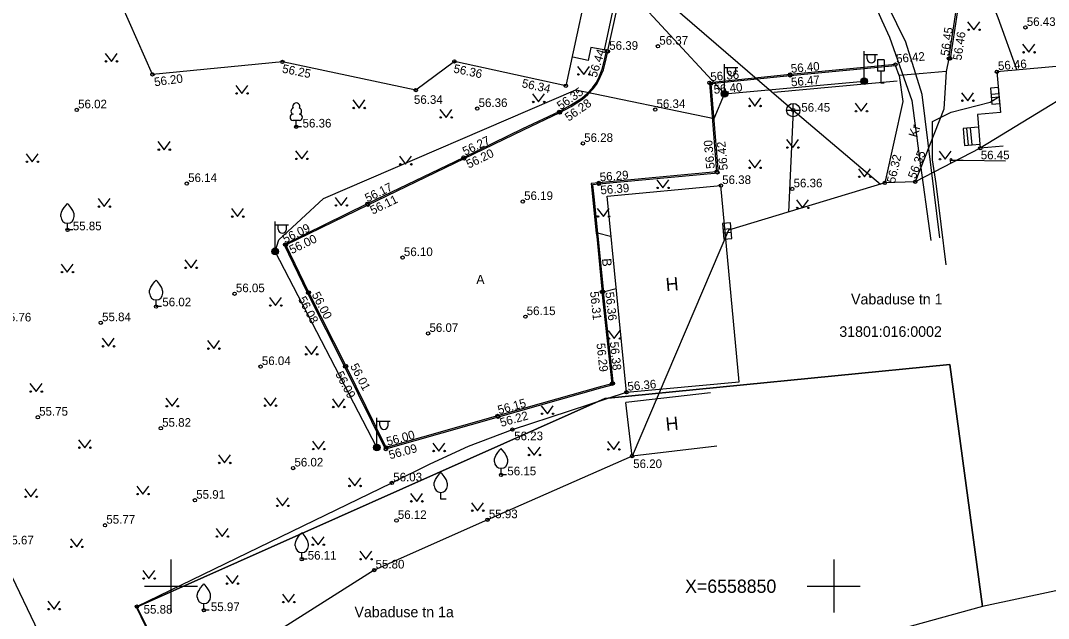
# Model space of a CAD drawing. Extents: x 542320 to 543602, y 6558748 to 6559969.
# Drawn here: x 543038.7 to 543116.2, y 6558847.6 to 6558892.7 of the extents above; entities that cross this region are included whole.
import ezdxf

# ---------------------------------------------------------------- set-up
doc = ezdxf.new("R2010")
doc.units = 0
for name, color, linetype in [('AED', 7, 'Continuous'), ('ELRAJATISMP', 7, 'Continuous'), ('HALJASTUS', 7, 'Continuous'), ('HOONE', 7, 'Continuous'), ('HOONEDET', 7, 'Continuous'), ('KKAEV', 7, 'Continuous'), ('KORGUS-EH2000', 7, 'Continuous'), ('KTRASS', 7, 'Continuous'), ('LIIKLUS', 7, 'Continuous'), ('mootpiir', 7, 'Continuous'), ('MPKAABEL', 7, 'Continuous'), ('PIIR', 7, 'Continuous'), ('POST', 7, 'Continuous'), ('PUU', 7, 'Continuous'), ('SITRASS', 7, 'Continuous'), ('TEE', 7, 'Continuous'), ('VORK', 7, 'Continuous'), ('VTRASS', 7, 'Continuous')]:
    doc.layers.add(name, color=color, linetype=linetype)

# ---------------------------------------------------------------- blocks, each defined once
blk = doc.blocks.new('VKORIS')
for p, q in [((0, 4), (0, -4)), ((-4, 0), (4, 0))]:
    blk.add_line(p, q)
blk = doc.blocks.new('LEHTP1')
for p, q in [((0.48, 0.95), (-0.48, 0.95)), ((0, 0), (0, 0.95)), ((0.76, 0), (0, 0))]:
    blk.add_line(p, q)
for centre, radius, start, end in [((0, 3.04), 0.554, 332.5799, 207.4201), ((-0.47, 1.42), 0.475, 90.0016, 269.3953), ((-0.34, 2.35), 0.465, 109.0217, 253.1415), ((0.34, 2.35), 0.465, 286.8508, 70.9859), ((0.47, 1.42), 0.475, 270.6047, 89.9984)]:
    blk.add_arc(centre, radius, start, end)
blk = doc.blocks.new('VILJA1')
for p, q in [((0, 0), (0, 1)), ((0.8, 0), (0, 0))]:
    blk.add_line(p, q)
for points in [[(-1, 2), (-1, 2.3), (-0.98, 2.43), (-0.91, 2.69), (-0.79, 2.93), (-0.5, 3.4), (-0.18, 3.81), (0, 4)], [(1, 2), (1, 2.3), (0.98, 2.43), (0.91, 2.69), (0.79, 2.93), (0.5, 3.4), (0.18, 3.81), (0, 4)]]:
    blk.add_lwpolyline(points)
blk.add_arc((0, 2), 1, 180, 0)
blk = doc.blocks.new('MEPOST')
for radius in [0.5, 0.45, 0.4, 0.35, 0.3, 0.25, 0.2, 0.15, 0.1, 0.05]:
    blk.add_circle((0, 0), radius)
blk = doc.blocks.new('VAPOST')
for p, q in [((0, 0.5), (0, 4.5)), ((0, 4), (2, 4)), ((0.45, 3.36), (0.45, 4)), ((1.68, 3.36), (1.68, 4))]:
    blk.add_line(p, q)
blk.add_arc((1.07, 3.36), 0.613, 180, 0)
blk = doc.blocks.new('KAKAEV')
for p, q in [((-1, 0), (1, 0)), ((0, -1), (0, 1))]:
    blk.add_line(p, q)
blk.add_circle((0, 0), 1)
blk = doc.blocks.new('LIIKLM')
for points in [[(-0.5, 3.5), (-0.5, 1.8)], [(0.5, 3.5), (-0.5, 3.5)], [(0.5, 3.5), (0.5, 1.8)], [(0.5, 1.8), (-0.5, 1.8)], [(0, 1.8), (0, 0)], [(0.5, 0), (0, 0)]]:
    blk.add_lwpolyline(points)
blk = doc.blocks.new('ELKAPP')
for p, q in [((1.19, 0.6), (-1.19, 0.6)), ((-1.19, 0.6), (-1.19, -0.6)), ((-0.27, 0.6), (-0.27, -0.6)), ((0.27, 0.6), (0.27, -0.6)), ((1.19, -0.6), (1.19, 0.6)), ((-1.19, -0.6), (1.19, -0.6))]:
    blk.add_line(p, q)
blk = doc.blocks.new('MURU')
for p, q in [((-0.93, 1.21), (0, 0)), ((0, 0), (0.89, 1.21))]:
    blk.add_line(p, q)
for centre in [(-0.8, 0), (0.86, 0)]:
    blk.add_circle(centre, 0.11)
blk = doc.blocks.new('RING02')
blk.add_circle((0, 0), 0.25)

msp = doc.modelspace()

# ---------------------------------------------------------------- linework, layer by layer
at = {"layer": 'AED'}
msp.add_lwpolyline([(543050.102, 6558843.068), (543047.43, 6558848.45), (543066.668, 6558857.787), (543069.546, 6558859.237), (543072.445, 6558860.561), (543075.754, 6558861.81), (543084.367, 6558864.629)], dxfattribs=at)
at = {"layer": 'HALJASTUS'}
for points in [[(543095.485, 6558887.284), (543104.792, 6558888.136)], [(543034.867, 6558857.188), (543041.705, 6558842.986)]]:
    msp.add_lwpolyline(points, dxfattribs=at)
at = {"layer": 'HOONE'}
msp.add_lwpolyline([(543034.683, 6558908.573), (543039.145, 6558923.204), (543048.898, 6558920.298), (543046.148, 6558911.034), (543052.456, 6558904.09), (543051.993, 6558903.334), (543059.743, 6558898.897), (543060.252, 6558899.636), (543066.159, 6558898.365), (543069.065, 6558900.487), (543081.93, 6558897.713), (543079.788, 6558887.775), (543071.384, 6558889.615), (543068.481, 6558887.445), (543058.412, 6558889.575), (543048.599, 6558888.632), (543044.558, 6558897.817)], close=True, dxfattribs=at)
for points in [[(543122.396, 6558889.719), (543112.307, 6558888.829)], [(543112.307, 6558888.829), (543112.578, 6558885.764), (543110.83, 6558885.608), (543111.054, 6558883.053)], [(543112.789, 6558883.207), (543111.054, 6558883.053)], [(543084.367, 6558864.629), (543082.902, 6558879.445), (543091.482, 6558880.238)], [(543092.852, 6558865.413), (543091.482, 6558880.238)], [(543084.367, 6558864.629), (543092.852, 6558865.413)], [(543090.709, 6558864.599), (543084.319, 6558863.86)], [(543084.787, 6558859.815), (543084.319, 6558863.86)], [(543091.177, 6558860.554), (543084.787, 6558859.815)]]:
    msp.add_lwpolyline(points, dxfattribs=at)
at = {"layer": 'HOONEDET'}
for points in [[(543082.952, 6558890.426), (543083.981, 6558895.123), (543081.515, 6558895.656)], [(543082.694, 6558890.46), (543083.714, 6558895.181)], [(543082.952, 6558890.426), (543081.685, 6558890.652), (543081.478, 6558889.69), (543080.315, 6558889.925)], [(543110.89, 6558884.655), (543109.75, 6558884.551)], [(543109.75, 6558884.551), (543109.872, 6558883.269)], [(543110.019, 6558884.577), (543110.141, 6558883.295)], [(543110.289, 6558884.602), (543110.411, 6558883.32)], [(543109.872, 6558883.269), (543111.006, 6558883.375)]]:
    msp.add_lwpolyline(points, dxfattribs=at)
at = {"layer": 'KTRASS'}
for points in [[(543080.977, 6558899.722), (543096.945, 6558885.936), (543103.523, 6558880.342)], [(543096.945, 6558885.936), (543096.591, 6558878.238)]]:
    msp.add_lwpolyline(points, dxfattribs=at)
at = {"layer": 'mootpiir'}
msp.add_lwpolyline([(543122.175, 6558889.852), (543111.054, 6558883.053), (543106.145, 6558880.527), (543103.846, 6558880.44), (543092.069, 6558876.865), (543084.787, 6558859.815), (543073.879, 6558855.007), (543065.335, 6558851.21), (543055.531, 6558844.994)], dxfattribs=at)
at = {"layer": 'MPKAABEL'}
for points in [[(543099.403, 6558906.806), (543099.315, 6558905.267), (543100.092, 6558903.434), (543101.085, 6558899.465), (543102.078, 6558896.251), (543103.632, 6558892.692), (543104.216, 6558891.45), (543105.878, 6558886.662), (543106.439, 6558882.477), (543107.325, 6558876.083)], [(543107.994, 6558876.298), (543106.677, 6558887.105), (543105.425, 6558891.061), (543102.749, 6558896.583), (543101.807, 6558899.724), (543100.957, 6558903.142), (543100.302, 6558904.938), (543099.403, 6558906.806)], [(543091.766, 6558887.156), (543083.836, 6558895.736), (543082.377, 6558896.34), (543081.695, 6558896.464)], [(543065.534, 6558860.459), (543057.87, 6558875.269), (543058.138, 6558876.129), (543061.501, 6558879.271), (543080.538, 6558887.458), (543090.987, 6558885.308), (543091.766, 6558887.156), (543102.293, 6558888.127)], [(543108.477, 6558874.253), (543107.714, 6558880.382), (543107.441, 6558882.176), (543107.447, 6558885.067), (543108.844, 6558885.773), (543111.805, 6558886.53), (543112.412, 6558886.9)]]:
    msp.add_lwpolyline(points, dxfattribs=at)
at = {"layer": 'PIIR'}
for points in [[(543035.44, 6558940.39), (543040.58, 6558937.38), (543133.64, 6558888.72), (543159.27, 6558882.37), (543180.35, 6558877.33), (543188.6, 6558877.87), (543138.85, 6558855), (543136.39, 6558853.9), (543124.53, 6558851.31), (543111.21, 6558848.45), (543108.75, 6558866.73), (543082.72, 6558864.15), (543047.4, 6558848.41), (543054.87, 6558832.91), (543045.52, 6558829.45), (543026.29, 6558871.02), (543014.78, 6558890.86), (543006.52, 6558905.62), (543035.44, 6558940.39)], [(543047.4, 6558848.41), (543082.72, 6558864.15), (543108.75, 6558866.73), (543111.21, 6558848.45), (543054.87, 6558832.91), (543047.4, 6558848.41)]]:
    msp.add_lwpolyline(points, dxfattribs=at)
at = {"layer": 'SITRASS'}
msp.add_lwpolyline([(543064.33, 6558898.99), (543071.83, 6558902.87), (543075.21, 6558904.44), (543076.8, 6558907.47), (543078.66, 6558910.58), (543079.69, 6558911.96), (543080.74, 6558912.11), (543085.83, 6558909.45), (543091.08, 6558906.71), (543100.42, 6558902.47), (543106.04, 6558900.15), (543110.07, 6558898.37), (543111.55, 6558895.04), (543112.38, 6558892.93), (543113.811, 6558888.962)], dxfattribs=at)
at = {"layer": 'TEE'}
for points in [[(543108.689, 6558889.82), (543109.568, 6558895.629), (543109.891, 6558898.021), (543110.141, 6558898.727), (543110.34, 6558899.159), (543110.783, 6558899.83), (543111.401, 6558900.39), (543112.037, 6558900.795), (543112.338, 6558900.922), (543113.762, 6558901.416), (543114.345, 6558901.49), (543115.119, 6558901.431), (543115.935, 6558901.296), (543116.696, 6558901.074), (543122.322, 6558898.427)], [(543108.808, 6558889.802), (543109.687, 6558895.612), (543110.008, 6558897.993), (543110.252, 6558898.682), (543110.445, 6558899.101), (543110.875, 6558899.751), (543111.474, 6558900.294), (543112.093, 6558900.688), (543112.381, 6558900.81), (543113.79, 6558901.299), (543114.348, 6558901.369), (543115.105, 6558901.312), (543115.908, 6558901.179), (543116.653, 6558900.961), (543122.271, 6558898.318)], [(543104.659, 6558889.273), (543096.719, 6558888.53), (543090.723, 6558887.916), (543091.269, 6558881.185), (543082.279, 6558880.338), (543081.812, 6558880.299), (543081.904, 6558879.393), (543082.185, 6558876.649), (543082.214, 6558876.408), (543082.614, 6558872.418), (543082.612, 6558872.209), (543083.371, 6558865.205), (543082.397, 6558864.948), (543074.671, 6558862.754), (543066.192, 6558860.347), (543063.117, 6558866.56), (543060.312, 6558872.129), (543058.534, 6558875.801), (543064.821, 6558878.881), (543072.071, 6558882.36), (543076.549, 6558884.535), (543079.295, 6558885.836), (543080.148, 6558886.297), (543080.987, 6558886.842), (543081.39, 6558887.187), (543081.794, 6558887.625), (543082.072, 6558887.997), (543082.293, 6558888.458), (543082.522, 6558889.019), (543082.661, 6558889.504), (543082.865, 6558890.393)], [(543104.65, 6558889.373), (543096.709, 6558888.63), (543090.615, 6558888.005), (543091.161, 6558881.275), (543082.27, 6558880.438), (543081.702, 6558880.39), (543081.805, 6558879.383), (543082.086, 6558876.638), (543082.115, 6558876.397), (543082.514, 6558872.413), (543082.512, 6558872.204), (543083.262, 6558865.28), (543082.371, 6558865.044), (543074.644, 6558862.85), (543066.245, 6558860.466), (543063.206, 6558866.605), (543060.402, 6558872.173), (543058.667, 6558875.755), (543064.865, 6558878.791), (543072.114, 6558882.27), (543076.592, 6558884.445), (543079.34, 6558885.747), (543080.199, 6558886.211), (543081.047, 6558886.762), (543081.46, 6558887.115), (543081.871, 6558887.561), (543082.158, 6558887.945), (543082.384, 6558888.417), (543082.617, 6558888.986), (543082.758, 6558889.479), (543082.962, 6558890.371)], [(543108.689, 6558889.82), (543108.49, 6558888.85), (543106.739, 6558888.704), (543104.928, 6558888.536), (543104.645, 6558889.294)], [(543104.928, 6558888.536), (543105.203, 6558886.58), (543103.846, 6558880.44)], [(543108.49, 6558888.85), (543108.302, 6558885.994), (543106.145, 6558880.527)], [(543082.17, 6558876.659), (543083.17, 6558876.429)], [(543082.614, 6558872.217), (543083.587, 6558872.473)]]:
    msp.add_lwpolyline(points, dxfattribs=at)
at = {"layer": 'VTRASS'}
msp.add_lwpolyline([(543108.832, 6558881.91), (543108.81, 6558882.166), (543109.749, 6558882.167), (543112.945, 6558882.118)], dxfattribs=at)

# ---------------------------------------------------------------- block references
at = {"layer": 'ELRAJATISMP', "xscale": 0.5, "yscale": 0.5, "rotation": -85.22702846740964}
for p in [(543112.178, 6558887.012), (543091.95, 6558876.811)]:
    msp.add_blockref('ELKAPP', p, dxfattribs=at)
at = {"layer": 'HALJASTUS', "xscale": 0.5, "yscale": 0.5}
for p in [(543110.565, 6558892.004), (543114.714, 6558890.302), (543045.503, 6558889.615), (543081.14, 6558888.626), (543055.349, 6558887.195), (543077.733, 6558886.548), (543094.05, 6558886.245), (543110.104, 6558886.645), (543064.193, 6558886.094), (543102.076, 6558885.853), (543070.755, 6558885.381), (543096.903, 6558883.105), (543049.485, 6558882.948), (543039.531, 6558882.034), (543059.869, 6558882.249), (543067.704, 6558881.843), (543094.047, 6558881.577), (543108.411, 6558882.227), (543102.33, 6558880.9), (543087.106, 6558880.062), (543044.965, 6558878.646), (543062.842, 6558878.739), (543097.643, 6558878.55), (543055.027, 6558877.894), (543082.621, 6558877.903), (543051.518, 6558874.027), (543042.183, 6558873.707), (543057.895, 6558871.179), (543083.434, 6558868.686), (543045.28, 6558868.102), (543053.225, 6558867.924), (543060.6, 6558867.496), (543039.829, 6558864.684), (543050.09, 6558863.58), (543057.501, 6558863.616), (543062.649, 6558863.519), (543078.4, 6558863.009), (543043.499, 6558860.447), (543061.135, 6558860.34), (543070.214, 6558860.194), (543077.399, 6558859.893), (543083.403, 6558860.317), (543054.043, 6558859.293), (543063.87, 6558857.556), (543039.437, 6558856.744), (543047.879, 6558856.943), (543058.425, 6558856.053), (543068.537, 6558856.396), (543073.133, 6558855.691), (543053.865, 6558853.739), (543042.891, 6558852.956), (543061.102, 6558853.115), (543064.701, 6558852.024), (543048.342, 6558850.57), (543054.633, 6558850.185), (543041.181, 6558848.256), (543058.879, 6558848.791)]:
    msp.add_blockref('MURU', p, dxfattribs=at)
at = {"layer": 'KKAEV', "xscale": 0.5, "yscale": 0.5}
msp.add_blockref('KAKAEV', (543096.945, 6558885.936), dxfattribs=at)
at = {"layer": 'KORGUS-EH2000', "xscale": 0.5, "yscale": 0.5}
for p in [(543114.459, 6558892.173), (543086.739, 6558890.757), (543082.882, 6558890.395), (543082.962, 6558890.371), (543108.689, 6558889.82), (543108.783, 6558889.833), (543058.412, 6558889.575), (543071.384, 6558889.615), (543104.65, 6558889.373), (543048.599, 6558888.632), (543096.706, 6558888.63), (543096.706, 6558888.56), (543112.307, 6558888.829), (543068.481, 6558887.445), (543079.788, 6558887.775), (543090.615, 6558888.005), (543090.717, 6558887.921), (543042.896, 6558885.954), (543073.109, 6558886.052), (543086.529, 6558885.974), (543096.945, 6558885.936), (543079.292, 6558885.802), (543079.34, 6558885.747), (543059.456, 6558884.68), (543081.072, 6558883.417), (543111.054, 6558883.053), (543072.078, 6558882.366), (543072.114, 6558882.27), (543091.161, 6558881.275), (543091.226, 6558881.23), (543106.145, 6558880.527), (543051.197, 6558880.388), (543082.27, 6558880.438), (543082.279, 6558880.362), (543091.482, 6558880.238), (543096.869, 6558879.989), (543103.846, 6558880.44), (543076.542, 6558879.031), (543064.815, 6558878.866), (543064.865, 6558878.791), (543042.2, 6558876.891), (543058.608, 6558875.777), (543058.667, 6558875.755), (543067.474, 6558874.797), (543054.8, 6558872.07), (543060.343, 6558872.148), (543060.402, 6558872.173), (543082.512, 6558872.204), (543082.598, 6558872.217), (543048.883, 6558871.102), (543044.703, 6558869.881), (543076.734, 6558870.34), (543069.4, 6558869.072), (543056.758, 6558866.569), (543063.13, 6558866.576), (543063.206, 6558866.605), (543083.262, 6558865.28), (543083.345, 6558865.299), (543084.367, 6558864.629), (543039.958, 6558862.749), (543074.644, 6558862.85), (543074.679, 6558862.778), (543049.237, 6558861.913), (543075.754, 6558861.81), (543066.201, 6558860.347), (543066.245, 6558860.466), (543084.787, 6558859.815), (543059.214, 6558858.912), (543074.904, 6558858.392), (543066.668, 6558857.787), (543051.807, 6558856.475), (543067.014, 6558854.95), (543073.879, 6558855.007), (543045.025, 6558854.591), (543059.873, 6558852.031), (543065.335, 6558851.21), (543047.43, 6558848.45), (543052.488, 6558848.173)]:
    msp.add_blockref('RING02', p, dxfattribs=at)
at = {"layer": 'LIIKLUS', "xscale": 0.5, "yscale": 0.5}
msp.add_blockref('LIIKLM', (543103.561, 6558887.971), dxfattribs=at)
at = {"layer": 'POST', "xscale": 0.5, "yscale": 0.5}
for name, p in [('VAPOST', (543102.293, 6558888.127)), ('VAPOST', (543091.766, 6558887.156)), ('MEPOST', (543102.293, 6558888.127)), ('MEPOST', (543091.766, 6558887.156)), ('VAPOST', (543057.87, 6558875.269)), ('MEPOST', (543057.87, 6558875.269)), ('VAPOST', (543065.534, 6558860.459)), ('MEPOST', (543065.534, 6558860.459))]:
    msp.add_blockref(name, p, dxfattribs=at)
at = {"layer": 'PUU', "xscale": 0.5, "yscale": 0.5}
for name, p in [('LEHTP1', (543059.456, 6558884.68)), ('VILJA1', (543042.2, 6558876.891)), ('VILJA1', (543048.883, 6558871.102)), ('VILJA1', (543074.904, 6558858.392)), ('VILJA1', (543070.358, 6558856.569)), ('VILJA1', (543059.873, 6558852.031)), ('VILJA1', (543052.488, 6558848.173))]:
    msp.add_blockref(name, p, dxfattribs=at)
at = {"layer": 'VORK', "xscale": 0.5, "yscale": 0.5}
for p in [(543050, 6558850), (543100, 6558850)]:
    msp.add_blockref('VKORIS', p, dxfattribs=at)

# ---------------------------------------------------------------- texts
at = {"layer": 'HOONE'}
for rotation, p in [(5.06456, (543087.365, 6558872.258)), (5.65681, (543087.365, 6558861.719))]:
    msp.add_text('H', height=1, rotation=rotation, dxfattribs=at).set_placement(p)
at = {"layer": 'KORGUS-EH2000'}
for s, p in [('56.43', (543114.559, 6558892.29)), ('56.37', (543086.839, 6558890.874)), ('56.39', (543083.062, 6558890.488)), ('56.34', (543068.329, 6558886.408)), ('56.36', (543073.209, 6558886.169)), ('56.02', (543042.996, 6558886.071)), ('56.34', (543086.629, 6558886.091)), ('56.45', (543097.551, 6558885.816)), ('56.36', (543059.928, 6558884.623)), ('56.28', (543081.172, 6558883.534)), ('56.45', (543111.087, 6558882.221)), ('56.14', (543051.297, 6558880.505)), ('56.38', (543091.582, 6558880.355)), ('56.36', (543096.969, 6558880.106)), ('56.19', (543076.642, 6558879.148)), ('55.85', (543042.596, 6558876.863)), ('56.10', (543067.574, 6558874.914)), ('56.05', (543054.9, 6558872.187)), ('56.02', (543049.349, 6558871.124)), ('55.76', (543037.285, 6558869.979)), ('55.84', (543044.803, 6558869.998)), ('56.15', (543076.834, 6558870.457)), ('56.07', (543069.5, 6558869.189)), ('56.04', (543056.858, 6558866.686)), ('55.75', (543040.058, 6558862.866)), ('55.82', (543049.337, 6558862.03)), ('56.23', (543075.891, 6558861.011)), ('56.02', (543059.314, 6558859.029)), ('56.15', (543075.375, 6558858.362)), ('56.20', (543084.869, 6558858.909)), ('56.03', (543066.768, 6558857.904)), ('55.91', (543051.907, 6558856.592)), ('55.93', (543073.979, 6558855.124)), ('55.77', (543045.125, 6558854.708)), ('56.12', (543067.114, 6558855.067)), ('55.67', (543037.477, 6558853.147)), ('56.11', (543060.316, 6558851.997)), ('55.80', (543065.435, 6558851.327)), ('55.88', (543047.938, 6558847.918)), ('55.97', (543053.011, 6558848.11))]:
    msp.add_text(s, height=0.65, dxfattribs=at).set_placement(p)
for s, rotation, p in [('56.45', 81.52325, (543108.68, 6558889.993)), ('56.46', 81.52325, (543109.625, 6558889.656)), ('56.44', 71.71076, (543082.093, 6558888.344)), ('56.42', 5.10865, (543104.731, 6558889.489)), ('56.25', 348.65946, (543058.351, 6558888.771)), ('56.36', 348.17214, (543071.272, 6558888.778)), ('56.40', 5.10865, (543096.79, 6558888.746)), ('56.46', 4.6004, (543112.408, 6558888.946)), ('56.20', 7.71541, (543048.777, 6558887.729)), ('56.36', 5.10865, (543090.716, 6558888.122)), ('56.47', 5.10865, (543096.803, 6558887.721)), ('56.34', 347.77932, (543076.425, 6558887.673)), ('56.35', 35.25322, (543079.402, 6558885.922)), ('56.40', 5.10865, (543090.966, 6558887.166)), ('56.28', 35.08748, (543080.005, 6558885.058)), ('56.27', 25.82251, (543072.185, 6558882.484)), ('56.20', 25.82251, (543072.469, 6558881.512)), ('56.30', 95.44404, (543091.031, 6558881.536)), ('56.42', 95.1984, (543092.013, 6558881.426)), ('56.32', 77.06321, (543104.616, 6558880.38)), ('56.35', 68.98006, (543106.17, 6558880.696)), ('56.29', 4.57741, (543082.371, 6558880.555)), ('56.17', 25.82251, (543064.821, 6558878.961)), ('56.39', 4.88361, (543082.425, 6558879.569)), ('56.11', 25.82251, (543065.219, 6558878.036)), ('56.09', 25.82251, (543058.614, 6558875.872)), ('56.00', 25.82251, (543059.117, 6558875.056)), ('56.00', 297.73009, (543060.602, 6558872.005)), ('56.31', 276.25124, (543081.607, 6558872.218)), ('56.36', 276.25124, (543082.765, 6558872.174)), ('56.08', 297.73009, (543059.57, 6558871.664)), ('56.29', 276.25124, (543082.098, 6558868.309)), ('56.38', 276.25124, (543083.102, 6558868.418)), ('56.01', 297.73009, (543063.498, 6558866.606)), ('56.09', 297.73009, (543062.38, 6558866.014)), ('56.36', 5.18031, (543084.469, 6558864.746)), ('56.15', 15.41671, (543074.748, 6558862.967)), ('56.22', 15.63258, (543074.922, 6558862.011)), ('56.00', 14.97573, (543066.349, 6558860.583)), ('56.09', 14.97573, (543066.528, 6558859.566))]:
    msp.add_text(s, height=0.65, rotation=rotation, dxfattribs=at).set_placement(p)
at = {"layer": 'PIIR'}
for s, p in [('Vabaduse tn 1', (543101.303, 6558871.266)), ('31801:016:0002', (543100.418, 6558868.815)), ('Vabaduse tn 1a', (543063.843, 6558847.645))]:
    msp.add_text(s, height=0.8, dxfattribs=at).set_placement(p)
at = {"layer": 'TEE'}
for s, rotation, p in [('Kr', 73.77399, (543106.295, 6558883.82)), ('B', 273.74559, (543082.517, 6558874.723))]:
    msp.add_text(s, height=0.7, rotation=rotation, dxfattribs=at).set_placement(p)
msp.add_text('A', height=0.7, dxfattribs=at).set_placement((543073.032, 6558872.797))
at = {"layer": 'VORK'}
msp.add_text('X=6558850', height=1, dxfattribs=at).set_placement((543088.785, 6558849.488))

doc.saveas('drawing.dxf')
